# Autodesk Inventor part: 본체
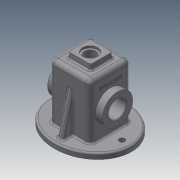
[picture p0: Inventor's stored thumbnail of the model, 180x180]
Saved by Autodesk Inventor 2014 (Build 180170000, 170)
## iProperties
Created: 2017-07
Part Number: 본체
Material: 알루미늄 6061
Document SubType Name: Modeling
Designer: user
Density: 2.71 g/cm^3
Appearance: 알루미늄 - 평지
Mass: 934.174 g
Surface Area: 1046.74 cm^2
Volume: 344.713 cm^3
Author: user
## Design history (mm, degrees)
sketch "스케치1"
  geometry: L1 (0, 0)-(74, 0); L2 (74, 0)-(74, 74); L3 (74, 74)-(0, 74); L4 (0, 74)-(0, 0)
  constraints: 8 end point, 2 parallel, 1 horizontal, 1 perpendicular
  dimensions: "d0" = 74 distance of L3.end L2.end; "d1" = 74 distance of L2.end L1.end
extrude "돌출1" new body sketch "스케치1" distance "d2" = 100; taper "d3" = 0 deg
feature "쉘1" dims "d4" = 5
node "작업 평면1"
sketch "스케치2"
  geometry: L1 (-13, 72.5)-(5, 72.5); L2 (5, 17.5)-(-13, 17.5); L3 (-44.131, 45)-(147.027, 45); L4 (-13, 61)-(12, 61); L5 (12, 29)-(-13, 29); L6 (0, 0)-(0, 100) reference; L7 (5, 0)-(5, 95) reference; L8 (5, 17.5)-(12, 24.5); L9 (5, 72.5)-(12, 65.5); L10 (-13, 17.5)-(-13, 29); L11 (-13, 61)-(-13, 72.5); L12 (12, 65.5)-(12, 61); L13 (12, 29)-(12, 24.5)
  constraints: 22 end point, 6 parallel, 2 horizontal, 2 perpendicular, 2 point on line
  dimensions: "d7" = 55 diameter of L1 L3; "d8" = 55 distance between parallel lines of L2 L1; "d9" = 32 distance of L4.end L5.start; "d10" = 32 diameter of L4 L3; "d11" = 13 distance from line of L2.end L6; "d13" = 135 deg angle of L8 L7; "d14" = 135 deg angle of L7 L9; "d16" = 32 distance between parallel lines of L4 L5; "d17" = 32 diameter of L5 L3 (derived); "d18" = 12 distance between parallel lines of L6 L12; "d19" = 18 distance between parallel lines of L11 L7; "d21" = 142.02745 distance from line of L3.end L7; "d22" = 49.1306 distance from line of L3.start L7; "d23" = 100 diameter of L7.end L3
revolve "회전1" sketch "스케치2" stored, may be unused: angle "d24" = 90 deg
sketch "스케치3"
  geometry: C1 r 16 at (0, 0) reference; C2 r 16 at (0, 0); 1 further point
  constraints: 1 centre point, 1 coincident, 1 concentric
extrude "돌출2" cut sketch "스케치3" distance "d25" = 110; taper "d26" = 0 deg
node "작업 평면2"
fillet "모깎기1" dims "d28" = 8
fillet "모깎기2" dims "d29" = 8
sketch "스케치4"
  geometry: L1 (17, 17)-(57, 17); L2 (57, 17)-(57, 57); L3 (57, 57)-(17, 57); L4 (17, 57)-(17, 17); L5 (-57.907, 37)-(110.5, 37); L6 (37, 107.884)-(37, -35.017); L7 (0, 66)-(0, 8) reference; L8 (8, 0)-(66, 0) reference; 1 further point
  constraints: 12 end point, 3 perpendicular, 2 parallel, 1 horizontal
  dimensions: "d30" = 40 distance of L3.end L2.end; "d31" = 40 distance of L2.end L1.end; "d32" = 20 distance between parallel lines of L5 L3; "d33" = 20 distance between parallel lines of L2 L6; "d34" = 37 distance between parallel lines of L7 L6; "d35" = 37 distance between parallel lines of L8 L5
extrude "돌출3" join sketch "스케치4" distance "d36" = 10; taper "d37" = 0 deg
sketch "스케치5"
  geometry: L1 (57, 57)-(17, 57) reference; L2 (17, 57)-(17, 17) reference; C1 r 14 at (37, 37); C2 r 10.5 at (37, 37); 1 further point
  constraints: 2 centre point, 1 coincident
  dimensions: "d38" = 28 diameter of C1; "d39" = 21 diameter of C2; "d40" = 20 distance from line of L2 C2.centre; "d41" = 20 distance from line of L1 C1.centre
extrude "돌출4" cut sketch "스케치5" distance "d42" = 45.5; taper "d43" = 0 deg
extrude "돌출5" cut sketch "스케치5" distance "d44" = 4; taper "d45" = 0 deg
sketch "스케치6"
  geometry: L1 (-38, 37)-(112, 37); L2 (37, 102)-(37, -28); C1 r 5 at (-21, 37); C2 r 5 at (95, 37); 5 further points; 1 other entity
  constraints: 4 end point, 3 coincident, 2 centre point, 2 point on line, 1 horizontal, 1 vertical, 6 other
  dimensions: "d48" = 37 horizontal distance of point (0, 0) point (37, 37); "d49" = 37 horizontal distance of point (0, 0) point (37, 37); "d51" = 65 distance of L2.start point (37, 37); "d52" = 75 distance of L1.end point (37, 37); "d53" = 0 distance from line of point (37, 37) L2; "d54" = 0 distance from line of point (37, 37) L1; "d55" = 116 distance of point (95, 37) point (-21, 37); "d56" = 58 distance of point (37, 37) point (95, 37); "d57" = 10 diameter of C1; "d58" = 10 diameter of C2
extrude "돌출6" join sketch "스케치6" distance "d59" = 10; taper "d60" = 0 deg
sketch "스케치7"
  geometry: L1 (102, 0)-(-28, 0) reference; L2 (-28, -10)-(102, -10) reference; L3 (-28, 0)-(-28, -10); L4 (102, 0)-(102, -10); L5 (70.326, 86.928)-(92, 0); L6 (2.673, 82.917)-(-18, 0); L7 (-18, 0)-(-19.247, -5); L8 (-19.247, -5)-(2.673, -5); L9 (2.673, -5)-(2.673, 82.917); L10 (70.326, 86.928)-(71.915, -5.161); L11 (71.915, -5.161)-(93.287, -5.161); L12 (93.287, -5.161)-(92, 0); 1 further point
  constraints: 20 end point, 3 perpendicular, 2 collinear, 2 parallel, 2 point on line
  dimensions: "d63" = 14 deg angle of L4 L5; "d64" = 10 distance from line of L4 L5.end; "d65" = 14 deg angle of L3 L6; "d66" = 10 distance of L1.end L6.end; "d67" = 89.012 deg angle of L10 L1; "d68" = 5.16065 distance between parallel lines of L11 L1; "d69" = 5 distance between parallel lines of L8 L1; "d70" = 99.32659 distance between parallel lines of L9 L4; "d71" = 30.17 distance from line of L1.start L10
extrude "돌출7" join sketch "스케치7" stored distance "d72" = 10; taper "d73" = 0 deg
fillet "모깎기3" dims "d74" = 3
fillet "모깎기4" dims "d75" = 3
fillet "모깎기5" dims "d76" = 3
feature "면 기울기3" dims angle "d77" = 5 deg
feature "면 기울기4" dims angle "d78" = 5 deg
feature "면 기울기5" dims angle "d79" = 5 deg
feature "면 기울기6" dims angle "d80" = 5 deg
fillet "모깎기6" dims "d81" = 3
fillet "모깎기7" dims "d82" = 3
sketch "스케치9"
  geometry: L1 (-69, 69)-(-5, 69); L2 (-5, 69)-(-5, 5); L3 (-5, 5)-(-69, 5); L4 (-69, 5)-(-69, 69); 2 further points; 1 other entity
  constraints: 8 end point, 2 parallel, 1 horizontal, 1 perpendicular, 1 other
  dimensions: "d84" = 32 distance from line of point (-37, 37) L2; "d85" = 32 distance from line of point (-37, 37) L1; "d86" = 64 distance between parallel lines of L3 L1; "d87" = 64 distance between parallel lines of L2 L4
extrude "돌출8" cut sketch "스케치9" distance "d88" = 10; taper "d89" = 0 deg
fillet "모깎기9" dims "d90" = 3
fillet "모깎기10" dims "d91" = 0.5
sketch "스케치10" dims "d92" = 45
  geometry: L1 (0, 0)-(22.5, 0); A1 r 16 centre (0, 0) between (-16, 0) and (16, 0) reference; 2 further points
  constraints: 2 coincident, 2 end point, 1 horizontal, 1 horizontal alignment, 2 other
hole "구멍1" sketch "스케치10" at (22.5, 0) diameter "d93" = 3.242; stored, may be unused: countersink angle "d97" = 90 deg, drill point angle "d99" = 118 deg; dims "d94" = 8, "d95" = 4, "d96" = 2, "d98" = 10
chamfer "모따기1" distance "d103" = 1; stored, may be unused: second distance "d104" = 2, angle "d105" = 45 deg
node "작업 평면3"
sketch "스케치11"
  geometry: L1 (-18, 12.863)-(-18, 46.011) reference; L2 (89, 66)-(0, 66) reference; 2 further points
  constraints: 1 other
  dimensions: "d107" = 30 distance from line of L1 point (12, 29); "d108" = 37 distance from line of L2 point (12, 29)
feature "엠보싱1" sketch "스케치11" dims "d7" = 55, "d8" = 55, "d9" = 32, "d10" = 32, "d11" = 13, "d13" = 135 deg, "d14" = 135 deg, "d16" = 32, "d17" = 32 (derived), "d18" = 12, "d19" = 18, "d21" = 142.02745, "d22" = 49.1306, "d23" = 100, "d109" = 0.5, "d110" = 0
fillet "모깎기11" dims "d111" = 3
node "솔리드1"
mirror "대칭1"
pattern_circular "원형 패턴1" dims angle "d101" = 360 deg
mirror "대칭2"
node "투영된 루프1"
other parameters: "d5" = -37, "d27" = 37, "d61" = 14 deg, "d62" = 14 deg, "d106" = 46.75
